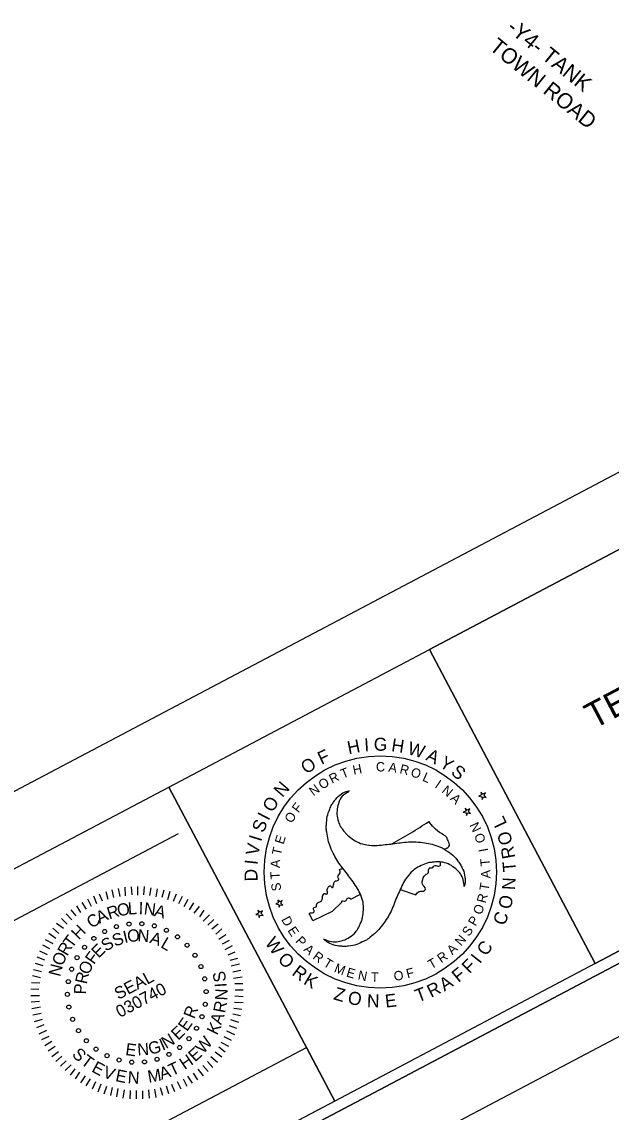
# Model space of a CAD drawing. Extents: x 1487052 to 1489663, y 496209 to 500965.
# Drawn here: x 1488873.2 to 1489101.4, y 498613.3 to 499035.6 of the extents above; entities that cross this region are included whole.
import ezdxf

# ---------------------------------------------------------------- set-up
doc = ezdxf.new("R2010")
doc.units = 0
for name, color, linetype in [('DEV TYPE 3 BARRICADE SECTION CELL', 7, 'Continuous'), ('DEV TYPE 3 BARRICADE SINGLE WITH R11-2 CELL', 7, 'Continuous'), ('DEV TYPE 3 BARRICADE WITH R11-4 M4-10L CELL', 7, 'Continuous'), ('DEV TYPE 3 BARRICADE WITH R11-4 M4-10R CELL', 7, 'Continuous'), ('Scratch_Level_0', 7, 'Continuous'), ('Scratch_Level_3', 7, 'Continuous'), ('Scratch_Level_4', 7, 'Continuous'), ('Sheet Plot Border Outside CELL', 7, 'Continuous'), ('Sheet Sticker Exception Certification CELL', 7, 'Continuous'), ('WZ OSDR CELL', 7, 'Continuous')]:
    doc.layers.add(name, color=color, linetype=linetype)

msp = doc.modelspace()

# ---------------------------------------------------------------- linework, layer by layer
at = {"layer": 'DEV TYPE 3 BARRICADE SINGLE WITH R11-2 CELL'}
msp.add_lwpolyline([(1488799.26, 499640.64), (1487561.25, 498986.94), (1488004.83, 498146.86), (1488782, 498557.22), (1488726.77, 498661.8), (1489187.62, 498905.14)], close=True, dxfattribs=at)
at = {"layer": 'DEV TYPE 3 BARRICADE WITH R11-4 M4-10L CELL'}
msp.add_circle((1489011.98, 498706.33), 44.97, dxfattribs=at)
at = {"layer": 'DEV TYPE 3 BARRICADE WITH R11-4 M4-10R CELL'}
for p, q in [((1489051.12, 498736.16), (1489050.16, 498735.65)), ((1489050.16, 498735.65), (1489051.24, 498735.49)), ((1489051.72, 498736.47), (1489050.94, 498737.19)), ((1489050.94, 498737.19), (1489051.12, 498736.16)), ((1489051.24, 498735.49), (1489051.45, 498734.42)), ((1489051.45, 498734.42), (1489051.89, 498735.38)), ((1489052.68, 498736.98), (1489051.72, 498736.47)), ((1489051.89, 498735.38), (1489052.98, 498735.23)), ((1489052.2, 498736), (1489052.68, 498736.98)), ((1489052.98, 498735.23), (1489052.2, 498736)), ((1489045.04, 498729.95), (1489044.08, 498729.45)), ((1489044.08, 498729.45), (1489045.16, 498729.29)), ((1489045.64, 498730.27), (1489044.85, 498730.99)), ((1489044.85, 498730.99), (1489045.04, 498729.95)), ((1489046.6, 498730.78), (1489045.64, 498730.27)), ((1489046.12, 498729.8), (1489046.6, 498730.78)), ((1489046.89, 498729.03), (1489046.12, 498729.8)), ((1489045.16, 498729.29), (1489045.36, 498728.22)), ((1489045.36, 498728.22), (1489045.81, 498729.18)), ((1489045.81, 498729.18), (1489046.89, 498729.03)), ((1489000.52, 498695.81), (1489004.26, 498697.75)), ((1489019.72, 498699.6), (1489025.71, 498697.48)), ((1488965.37, 498690.72), (1488964.59, 498691.44)), ((1488964.59, 498691.44), (1488964.77, 498690.4)), ((1488972.45, 498694.44), (1488971.49, 498693.94)), ((1488971.49, 498693.94), (1488972.57, 498693.78)), ((1488973.05, 498694.76), (1488972.27, 498695.48)), ((1488972.27, 498695.48), (1488972.45, 498694.44)), ((1488972.57, 498693.78), (1488972.78, 498692.71)), ((1488972.78, 498692.71), (1488973.22, 498693.67)), ((1488974.01, 498695.27), (1488973.05, 498694.76)), ((1488973.22, 498693.67), (1488974.3, 498693.51)), ((1488973.53, 498694.29), (1488974.01, 498695.27)), ((1488974.3, 498693.51), (1488973.53, 498694.29)), ((1488996.98, 498694.58), (1488993.39, 498691.09)), ((1488964.77, 498690.4), (1488963.81, 498689.89)), ((1488963.81, 498689.89), (1488964.89, 498689.74)), ((1488964.89, 498689.74), (1488965.1, 498688.67)), ((1488965.1, 498688.67), (1488965.54, 498689.63)), ((1488966.33, 498691.23), (1488965.37, 498690.72)), ((1488965.54, 498689.63), (1488966.63, 498689.47)), ((1488965.54, 498689.63), (1488966.62, 498689.47)), ((1488965.85, 498690.25), (1488966.33, 498691.23)), ((1488965.85, 498690.24), (1488966.33, 498691.23)), ((1488966.63, 498689.47), (1488965.85, 498690.25)), ((1488966.62, 498689.47), (1488965.85, 498690.24)), ((1488985.83, 498687.45), (1488984.66, 498689.83)), ((1488993.39, 498691.09), (1488985.83, 498687.45))]:
    msp.add_line(p, q, dxfattribs=at)
for start, end in [(299.0386, 303.1587), (293.5136, 293.8113)]:
    msp.add_arc((1488903.21, 498921.08), 233.19, start, end, dxfattribs=at)
for points in [[(1488999.78, 498737.85), (1488999.75, 498737.74), (1488997.69, 498736.12), (1488996.19, 498733.96), (1488995.45, 498731.5), (1488995.19, 498728.72), (1488995.76, 498725.81), (1488996.63, 498723.87), (1488997.27, 498723.05), (1488998.32, 498721.6), (1488999.32, 498720.55), (1489001.66, 498718.84), (1489004.37, 498717.42), (1489007.57, 498716.77), (1489007.84, 498716.73), (1489010.8, 498716.63), (1489013.9, 498716.92), (1489016.82, 498717.25), (1489019.85, 498717.67), (1489022.89, 498718), (1489025.82, 498717.97), (1489029.17, 498717.67), (1489032, 498717.07), (1489034.92, 498716.04), (1489036.31, 498715.46), (1489037.41, 498714.71), (1489040.01, 498712.89), (1489042.05, 498710.51), (1489043.14, 498708.96), (1489043.85, 498707.51), (1489043.97, 498707.28), (1489044.75, 498704.38), (1489044.74, 498701.58), (1489044.48, 498700.68)], [(1488989.98, 498680.47), (1488992.46, 498679.5), (1488995.04, 498679.28), (1488997.55, 498679.88), (1489000.11, 498681.05), (1489002.34, 498682.99), (1489003.58, 498684.73), (1489003.99, 498685.67), (1489004.71, 498687.3), (1489005.08, 498688.71), (1489005.45, 498691.58), (1489005.29, 498694.65), (1489004.27, 498697.73), (1489004.17, 498697.98), (1489002.74, 498700.62), (1489000.97, 498703.12), (1488999.22, 498705.5), (1488997.33, 498707.93), (1488995.5, 498710.37), (1488994.09, 498712.93), (1488992.69, 498715.99), (1488991.77, 498718.75), (1488991.23, 498721.8), (1488991.02, 498723.27), (1488991.11, 498724.6), (1488991.42, 498727.76), (1488992.43, 498730.72), (1488993.23, 498732.43), (1488994.14, 498733.75), (1488994.29, 498733.98), (1488996.38, 498736.12), (1488998.8, 498737.52), (1488999.75, 498737.74)], [(1489036.74, 498715.2), (1489038.78, 498716.62), (1489038.19, 498718.51), (1489037.45, 498719.98), (1489035.66, 498721.18), (1489032.69, 498723.54), (1489030.76, 498725.87)], [(1489044.48, 498700.68), (1489044.09, 498703.27), (1489042.99, 498705.63), (1489041.21, 498707.52), (1489038.93, 498709.13), (1489036.14, 498710.09), (1489034.03, 498710.31), (1489032.98, 498710.16), (1489031.23, 498710.02), (1489029.78, 498709.61), (1489027.15, 498708.5), (1489024.54, 498706.82), (1489022.4, 498704.38), (1489022.24, 498704.18), (1489020.67, 498701.62), (1489019.38, 498698.84), (1489018.16, 498696.14), (1489017.03, 498693.29), (1489015.81, 498690.46), (1489014.31, 498687.97), (1489012.37, 498685.21), (1489010.43, 498683.07), (1489008.09, 498681.07), (1489006.88, 498680.13), (1489005.69, 498679.57), (1489002.84, 498678.24), (1488999.73, 498677.63), (1488997.88, 498677.47), (1488996.25, 498677.62), (1488995.98, 498677.62), (1488993.09, 498678.37), (1488990.68, 498679.77), (1488989.98, 498680.47)], [(1489025.71, 498697.48), (1489026.97, 498698.72), (1489028.47, 498698.91), (1489029.13, 498699.13), (1489029.43, 498699.76), (1489028.29, 498701.56), (1489028.25, 498702.66), (1489029.48, 498705.23), (1489030.59, 498706.16), (1489030.91, 498707.8), (1489031.29, 498707.97), (1489032.04, 498707.95), (1489033.18, 498708.87), (1489034.64, 498708.59), (1489035.22, 498708.95), (1489035.2, 498710.15)], [(1488984.66, 498689.83), (1488984.47, 498690.02), (1488984.74, 498690.48), (1488986.07, 498690.61), (1488986.37, 498691.38), (1488986.1, 498691.84), (1488986.3, 498692.55), (1488987.13, 498692.8), (1488987.35, 498694), (1488987.88, 498694.51), (1488989.21, 498695.21), (1488989.95, 498697.61), (1488990.55, 498698.05), (1488990.95, 498697.72), (1488991.38, 498697.86), (1488991.4, 498699.53), (1488991.48, 498699.79), (1488992.42, 498700.93), (1488992.87, 498700.85), (1488993.28, 498700.33), (1488993.5, 498700.32), (1488993.76, 498700.81), (1488993.94, 498701.8), (1488994.66, 498702.85), (1488995.89, 498703.3), (1488995.59, 498704.36), (1488996.46, 498705.97), (1488996.45, 498706.67), (1488996.23, 498707.26)], [(1489000.52, 498695.81), (1488999.92, 498696.23), (1488999.22, 498696.09), (1488998.62, 498695.23), (1488998.01, 498694.93), (1488997.07, 498695.08), (1488996.98, 498694.58)]]:
    msp.add_spline(points, degree=3, dxfattribs=at)
at = {"layer": 'Scratch_Level_0'}
for p, q in [((1488804.45, 498652.85), (1488933.86, 498721.18)), ((1488941.13, 498718.44), (1488994.36, 498617.64))]:
    msp.add_line(p, q, dxfattribs=at)
for points in [[(1488820.13, 499708.2), (1487493.69, 499007.81), (1487983.96, 498079.29), (1489310.41, 498779.69)], [(1489239.66, 498902.65), (1489030.97, 498792.46), (1489095.17, 498670.86), (1489303.86, 498781.06)], [(1488930.15, 498739.23), (1489030.97, 498792.46), (1489095.17, 498670.86), (1488994.36, 498617.63)], [(1488753.26, 498645.82), (1488930.15, 498739.23), (1488994.36, 498617.63), (1488817.47, 498524.23)]]:
    msp.add_lwpolyline(points, close=True, dxfattribs=at)
at = {"layer": 'Scratch_Level_3'}
msp.add_lwpolyline([(1487493.69, 499007.81), (1488662.1, 499625.77), (1488820.13, 499708.2), (1489310.41, 498779.69), (1487983.96, 498079.29)], close=True, dxfattribs=at)
msp.add_lwpolyline([(1487493.69, 499007.81), (1488662.1, 499625.77), (1488820.13, 499708.2), (1489310.41, 498779.69), (1487983.96, 498079.29)], close=True, dxfattribs=at)
at = {"layer": 'Scratch_Level_4'}
for p, q in [((1488910.48, 498699.92), (1488911.11, 498696.86)), ((1488913.15, 498700.48), (1488913.23, 498697.13)), ((1488915.5, 498700.59), (1488915.85, 498697.52)), ((1488917.96, 498700.76), (1488918.03, 498697.4)), ((1488920.64, 498700.76), (1488920.27, 498697.45)), ((1488923.17, 498700.26), (1488922.68, 498697.17)), ((1488925.64, 498699.86), (1488925.04, 498696.72)), ((1488898.61, 498695.91), (1488900.12, 498693.04)), ((1488900.93, 498697.14), (1488902.11, 498694.09)), ((1488903.2, 498697.91), (1488904.38, 498695.14)), ((1488905.7, 498698.81), (1488906.55, 498695.86)), ((1488908.03, 498699.47), (1488908.66, 498696.41)), ((1488928.16, 498699.36), (1488927.45, 498696.44)), ((1488930.47, 498698.74), (1488929.59, 498695.59)), ((1488932.95, 498697.79), (1488931.79, 498694.91)), ((1488935.32, 498696.78), (1488933.82, 498694.01)), ((1488937.47, 498695.65), (1488935.97, 498692.88)), ((1488892.21, 498691.69), (1488894.17, 498689.33)), ((1488894.36, 498693.24), (1488895.98, 498690.71)), ((1488896.4, 498694.46), (1488898.13, 498691.99)), ((1488939.68, 498694.42), (1488938.01, 498691.7)), ((1488941.84, 498693.01), (1488939.83, 498690.39)), ((1488943.71, 498691.6), (1488941.98, 498688.99)), ((1488888.6, 498688.36), (1488890.77, 498686.12)), ((1488890.35, 498690.14), (1488892.58, 498687.78)), ((1488945.82, 498689.74), (1488943.42, 498687.34)), ((1488947.6, 498687.99), (1488945.24, 498685.76)), ((1488885.21, 498684.6), (1488887.55, 498682.58)), ((1488886.63, 498686.47), (1488889.35, 498684.52)), ((1488949.26, 498686.19), (1488946.79, 498684.17)), ((1488950.7, 498684.26), (1488948.34, 498682.31)), ((1488882.29, 498680.23), (1488885.23, 498678.67)), ((1488883.69, 498682.66), (1488886.42, 498680.71)), ((1488952.14, 498682.06), (1488949.45, 498680.21)), ((1488953.48, 498679.79), (1488950.72, 498678.33)), ((1488880.1, 498675.82), (1488883.09, 498674.43)), ((1488881.16, 498678.08), (1488883.99, 498676.74)), ((1488954.59, 498677.69), (1488951.83, 498676.23)), ((1488955.7, 498675.31), (1488952.93, 498674.13)), ((1488878.41, 498670.97), (1488881.4, 498670.14)), ((1488879.09, 498673.45), (1488881.96, 498672.28)), ((1488956.71, 498672.87), (1488953.76, 498672.03)), ((1488957.49, 498670.6), (1488954.31, 498669.91)), ((1488877.4, 498666.2), (1488880.44, 498665.54)), ((1488877.68, 498668.61), (1488880.78, 498667.84)), ((1488958.04, 498668.21), (1488954.87, 498667.52)), ((1488876.96, 498663.56), (1488880.15, 498663.41)), ((1488958.55, 498665.65), (1488955.15, 498665.12)), ((1488958.83, 498662.97), (1488955.7, 498663.01)), ((1488876.67, 498661.15), (1488879.86, 498660.99)), ((1488876.68, 498658.46), (1488880.03, 498658.54)), ((1488958.94, 498657.94), (1488955.69, 498658.2)), ((1488958.94, 498660.62), (1488955.86, 498660.55)), ((1488876.84, 498656.01), (1488880.08, 498656.3)), ((1488877.07, 498653.44), (1488880.41, 498654.07)), ((1488958.38, 498653.12), (1488955.24, 498653.44)), ((1488958.88, 498655.65), (1488955.52, 498655.85)), ((1488877.51, 498650.99), (1488880.69, 498651.68)), ((1488878.19, 498648.38), (1488881.24, 498649.28)), ((1488957.87, 498650.59), (1488954.84, 498651.25)), ((1488878.97, 498646.1), (1488881.9, 498647.23)), ((1488879.97, 498643.66), (1488882.9, 498645.07)), ((1488956.47, 498645.75), (1488953.65, 498646.81)), ((1488957.26, 498648), (1488954.16, 498649.05)), ((1488880.97, 498641.5), (1488883.85, 498642.74)), ((1488882.19, 498639.18), (1488884.84, 498640.86)), ((1488954.39, 498641.12), (1488951.57, 498642.45)), ((1488955.63, 498643.33), (1488952.53, 498644.66)), ((1488883.47, 498637.03), (1488886.17, 498638.88)), ((1488884.86, 498634.94), (1488887.39, 498636.84)), ((1488950.62, 498634.61), (1488948.01, 498636.62)), ((1488951.98, 498636.59), (1488949.42, 498638.49)), ((1488953.38, 498638.75), (1488950.44, 498640.31)), ((1488886.36, 498632.9), (1488888.77, 498635.02)), ((1488888.13, 498631.15), (1488890.43, 498633.22)), ((1488947.19, 498630.67), (1488945.12, 498632.97)), ((1488948.99, 498632.61), (1488946.43, 498634.79)), ((1488890.01, 498629.46), (1488892.26, 498631.63)), ((1488892.07, 498627.72), (1488893.91, 498630.11)), ((1488893.94, 498626.3), (1488895.73, 498628.8)), ((1488941.37, 498625.9), (1488939.63, 498628.38)), ((1488943.51, 498627.46), (1488941.5, 498629.93)), ((1488945.32, 498629.12), (1488943.26, 498631.42)), ((1488896.05, 498624.73), (1488897.89, 498627.4)), ((1488898.08, 498623.54), (1488899.76, 498626.26)), ((1488900.57, 498622.31), (1488901.85, 498625.25)), ((1488902.83, 498621.24), (1488903.88, 498624.34)), ((1488932.41, 498621.17), (1488931.34, 498624)), ((1488934.85, 498622.18), (1488933.44, 498625.11)), ((1488937.23, 498623.29), (1488935.77, 498626.06)), ((1488939.27, 498624.51), (1488937.53, 498627.27)), ((1488905.09, 498620.46), (1488906.19, 498623.44)), ((1488907.67, 498619.84), (1488908.33, 498622.88)), ((1488909.98, 498619.22), (1488910.52, 498622.48)), ((1488912.51, 498618.72), (1488912.94, 498621.92)), ((1488915.14, 498618.55), (1488915.29, 498621.74)), ((1488917.6, 498618.44), (1488917.58, 498621.68)), ((1488920.12, 498618.5), (1488920.05, 498621.57)), ((1488922.68, 498618.72), (1488922.39, 498621.96)), ((1488925.19, 498619.06), (1488924.68, 498622.18)), ((1488927.75, 498619.84), (1488926.9, 498622.78)), ((1488930.14, 498620.4), (1488929.23, 498623.45))]:
    msp.add_line(p, q, dxfattribs=at)
for centre in [(1488905.26, 498683.29), (1488909.85, 498685.18), (1488914.7, 498686.18), (1488919.66, 498686.28), (1488924.55, 498685.47), (1488929.2, 498683.77), (1488901.1, 498680.6), (1488933.47, 498681.24), (1488937.2, 498677.98), (1488897.5, 498677.19), (1488940.26, 498674.08), (1488894.6, 498673.17), (1488942.56, 498669.69), (1488892.48, 498668.69), (1488891.21, 498663.9), (1488944.01, 498664.95), (1488890.86, 498658.96), (1488944.57, 498660.03), (1488891.41, 498654.03), (1488944.21, 498655.08), (1488892.86, 498649.29), (1488942.95, 498650.29), (1488895.16, 498644.9), (1488940.83, 498645.81), (1488898.23, 498641), (1488937.92, 498641.79), (1488901.95, 498637.74), (1488930.16, 498635.69), (1488934.32, 498638.38), (1488906.22, 498635.21), (1488910.88, 498633.52), (1488915.77, 498632.7), (1488920.72, 498632.8), (1488925.57, 498633.81)]:
    msp.add_circle(centre, 0.788, dxfattribs=at)
at = {"layer": 'Sheet Plot Border Outside CELL'}
msp.add_lwpolyline([(1487851.5, 497981.08), (1489344.19, 498769.26), (1488830.57, 499741.98), (1487337.88, 498953.8)], close=True, dxfattribs=at)
at = {"layer": 'Sheet Sticker Exception Certification CELL'}
for p, q in [((1488806.49, 498545.01), (1488983.38, 498638.41)), ((1488983.39, 498638.4), (1488994.36, 498617.62)), ((1488994.36, 498617.63), (1488817.47, 498524.23))]:
    msp.add_line(p, q, dxfattribs=at)
at = {"layer": 'WZ OSDR CELL'}
msp.add_lwpolyline([(1489030.97, 498792.46), (1489239.66, 498902.65), (1489303.86, 498781.06), (1489095.17, 498670.86)], close=True, dxfattribs=at)

# ---------------------------------------------------------------- texts
at = {"layer": 'DEV TYPE 3 BARRICADE SECTION CELL'}
for s, p in [('-Y4- TANK', (1489060.55, 499032.49)), ('TOWN ROAD', (1489053.81, 499025.08))]:
    msp.add_text(s, height=6, rotation=320.9669, dxfattribs=at).set_placement(p)
at = {"layer": 'DEV TYPE 3 BARRICADE WITH R11-4 M4-10L CELL'}
for s, height, rotation, p in [('T', 3.63, 21.6235, (1488997.47, 498742.44)), ('L', 5.04, 115.2641, (1489061.15, 498725)), ('O', 5.04, 106.8247, (1489063.36, 498717.58)), ('R', 5.04, 100.587, (1489064.28, 498711.93)), ('T', 5.04, 94.7161, (1489064.58, 498706.55)), ('N', 5.04, 86.7271, (1489064.1, 498699.24)), ('O', 5.04, 78.2877, (1489062.49, 498691.67)), ('C', 5.04, 70.9158, (1489060.19, 498685.31)), ('W', 5.04, 305.9851, (1488967.14, 498678.84)), ('C', 5.04, 55.8384, (1489053.07, 498673.49)), ('O', 5.04, 314.9498, (1488971.98, 498672.19)), ('I', 5.04, 51.5854, (1489050.52, 498670.54)), ('R', 5.04, 323.3892, (1488977.42, 498666.69)), ('F', 5.04, 45.5978, (1489046.57, 498666.71)), ('K', 5.04, 329.6269, (1488981.93, 498663.17)), ('F', 5.04, 39.6102, (1489042.25, 498663.32)), ('T', 5.04, 20.5299, (1489026.53, 498655.79)), ('R', 5.04, 26.4007, (1489031.62, 498657.54)), ('A', 5.04, 32.6385, (1489036.81, 498659.96)), ('Z', 5.04, 344.0038, (1488993.59, 498657.06)), ('O', 5.04, 350.3584, (1488999.16, 498655.32)), ('N', 5.04, 358.7977, (1489006.78, 498653.99)), ('E', 5.04, 6.7868, (1489014.11, 498653.78))]:
    msp.add_text(s, height=height, rotation=rotation, dxfattribs=at).set_placement(p)
at = {"layer": 'DEV TYPE 3 BARRICADE WITH R11-4 M4-10R CELL'}
for s, height, rotation, p in [('H', 5.04, 11.2891, (1488999.74, 498751.88)), ('I', 5.04, 3.6391, (1489005.91, 498753.03)), ('G', 5.04, 359.3518, (1489009.42, 498753.31)), ('H', 5.04, 351.2983, (1489016.03, 498753.12)), ('W', 5.04, 343.6484, (1489022.22, 498752.09)), ('F', 5.04, 25.0926, (1488989.21, 498747.78)), ('A', 5.04, 334.6113, (1489029.28, 498749.82)), ('Y', 5.04, 327.5835, (1489034.47, 498747.31)), ('O', 5.04, 33.6, (1488983.31, 498744.04)), ('H', 3.63, 11.4673, (1489001.7, 498743.96)), ('C', 3.63, 1.3112, (1489010.34, 498745.22)), ('A', 3.63, 351.155, (1489014.96, 498745.25)), ('R', 3.63, 346.0769, (1489019.24, 498744.63)), ('O', 3.63, 340.9988, (1489023.44, 498743.55)), ('S', 5.04, 321.06, (1489038.98, 498744.42)), ('O', 3.63, 31.7797, (1488989.44, 498738.15)), ('R', 3.63, 26.7016, (1488993.27, 498740.48)), ('L', 3.63, 335.9207, (1489028, 498741.8)), ('N', 5.04, 49.4212, (1488974.09, 498734.95)), ('N', 3.63, 36.8577, (1488986.11, 498735.58)), ('I', 3.63, 325.7646, (1489032.8, 498739.24)), ('N', 3.63, 320.6865, (1489035.49, 498737.38)), ('O', 5.04, 57.9286, (1488970.26, 498729.11)), ('A', 3.63, 315.6084, (1489038.8, 498734.54)), ('I', 5.04, 62.2159, (1488968.67, 498725.97)), ('F', 3.63, 52.092, (1488980.29, 498728.98)), ('S', 5.04, 68.4199, (1488966.8, 498721.24)), ('O', 3.63, 57.1701, (1488977.67, 498724.94)), ('N', 3.63, 115.5681, (1489051.22, 498722.91)), ('O', 3.63, 110.762, (1489052.94, 498718.31)), ('V', 5.04, 79.4157, (1488964.77, 498712.46)), ('I', 5.04, 72.7073, (1488965.81, 498717.86)), ('E', 3.63, 72.4043, (1488974.48, 498716.82)), ('T', 3.63, 77.4824, (1488973.5, 498712.56)), ('I', 3.63, 100.6058, (1489053.74, 498714.49)), ('I', 5.04, 83.703, (1488964.44, 498708.95)), ('A', 3.63, 87.6386, (1488973.09, 498707.84)), ('T', 3.63, 95.5277, (1489054.49, 498708.78)), ('D', 5.04, 91.2941, (1488964.5, 498702.72)), ('T', 3.63, 92.7167, (1488973.15, 498703.59)), ('A', 3.63, 90.4496, (1489054.55, 498703.91)), ('S', 3.63, 97.7948, (1488973.68, 498699.18)), ('T', 3.63, 80.2935, (1489053.87, 498698.87)), ('R', 3.63, 75.2154, (1489052.74, 498694.04)), ('O', 3.63, 70.1373, (1489051.14, 498689.51)), ('D', 3.63, 298.1071, (1488973.56, 498687.97)), ('P', 3.63, 59.9811, (1489048.86, 498685.11)), ('E', 3.63, 303.1852, (1488975.93, 498683.72)), ('S', 3.63, 54.903, (1489046.28, 498681.14)), ('P', 3.63, 313.3414, (1488978.9, 498679.4)), ('N', 3.63, 49.825, (1489043.26, 498677.42)), ('A', 3.63, 318.4194, (1488982.04, 498676.02)), ('R', 3.63, 323.4975, (1488985.54, 498672.97)), ('R', 3.63, 34.5907, (1489035.57, 498670.92)), ('A', 3.63, 44.7469, (1489039.86, 498674.06)), ('T', 3.63, 328.5756, (1488989.62, 498670.14)), ('M', 3.63, 338.7318, (1488993.84, 498667.74)), ('T', 3.63, 29.5126, (1489031.71, 498668.61)), ('E', 3.63, 343.8099, (1488998.58, 498665.92)), ('N', 3.63, 348.8879, (1489003.08, 498664.72)), ('T', 3.63, 359.0441, (1489008.34, 498663.84)), ('O', 3.63, 9.2003, (1489017.48, 498664.12)), ('F', 3.63, 14.2784, (1489022.52, 498665.11))]:
    msp.add_text(s, height=height, rotation=rotation, dxfattribs=at).set_placement(p)
at = {"layer": 'Scratch_Level_0'}
msp.add_text('TEMPORARY TRAFFIC', height=10, rotation=27.8351, dxfattribs=at).set_placement((1489094.6, 498761.5))
at = {"layer": 'Scratch_Level_4'}
for s, height, rotation, p in [('A', 4.72, 25.81, (1488903.29, 498686.23)), ('R', 4.72, 17.8566, (1488907.06, 498687.93)), ('O', 4.72, 10.9219, (1488910.56, 498689.07)), ('L', 4.72, 3.581, (1488914.4, 498689.83)), ('I', 4.72, 358.641, (1488918.42, 498689.97)), ('N', 4.72, 352.7389, (1488920.26, 498689.96)), ('A', 4.72, 344.8402, (1488924.14, 498689.32)), ('C', 4.72, 32.775, (1488900.2, 498684.32)), ('H', 4.72, 45.5784, (1488895.22, 498679.84)), ('I', 4.7, 13.3172, (1488913.02, 498678.78)), ('O', 4.7, 5.71, (1488914.24, 498679.15)), ('N', 4.7, 355.2281, (1488917.87, 498679.51)), ('R', 4.72, 60.0105, (1488890.77, 498673.54)), ('T', 4.72, 53.2709, (1488892.61, 498676.49)), ('E', 4.7, 44.424, (1488902.92, 498672.74)), ('S', 4.7, 32.3031, (1488905.77, 498675.38)), ('S', 4.7, 20.8765, (1488909.25, 498677.36)), ('A', 4.7, 341.7789, (1488922.41, 498678.94)), ('L', 4.7, 329.3674, (1488926.64, 498677.35)), ('O', 4.72, 67.7793, (1488889.01, 498669.64)), ('F', 4.7, 54.235, (1488901.13, 498670.24)), ('N', 4.72, 75.9017, (1488888.04, 498665.59)), ('O', 4.7, 66.0869, (1488899.15, 498666.23)), ('R', 4.7, 77.5829, (1488898.34, 498662.69)), ('SEAL', 4.699, 27.8351, (1488910.59, 498656.77)), ('S', 4.72, 100.093, (1488952.4, 498664.11)), ('P', 4.7, 87.9587, (1488898.08, 498658.88)), ('030740', 4.699, 27.8351, (1488911.17, 498649.78)), ('I', 4.72, 93.8815, (1488952.61, 498661.84)), ('N', 4.72, 87.2077, (1488952.7, 498656.51)), ('R', 4.7, 68.1844, (1488939.96, 498649.19)), ('R', 4.72, 78.9854, (1488951.87, 498651.49)), ('E', 4.7, 54.9919, (1488937.16, 498644.32)), ('A', 4.72, 71.3568, (1488950.38, 498646.93)), ('E', 4.7, 43.6408, (1488933.71, 498640.94)), ('K', 4.72, 63.9761, (1488948.8, 498642.89)), ('G', 4.7, 15.3163, (1488922.87, 498635.5)), ('I', 4.7, 23.4597, (1488927.7, 498637.06)), ('N', 4.7, 30.9629, (1488929.03, 498637.76)), ('W', 4.72, 49.8409, (1488943.51, 498635.63)), ('S', 4.72, 316.0471, (1488892.33, 498635.38)), ('E', 4.7, 352.7043, (1488913.14, 498635.45)), ('N', 4.7, 3.8935, (1488918.07, 498635.23)), ('E', 4.72, 41.9998, (1488940.25, 498632.55)), ('T', 4.72, 323.4595, (1488895.7, 498632.18)), ('E', 4.72, 331.6576, (1488899.92, 498629.2)), ('T', 4.72, 25.2217, (1488931.36, 498627.19)), ('H', 4.72, 33.8463, (1488936.23, 498629.61)), ('V', 4.72, 339.7649, (1488904.27, 498627.01)), ('E', 4.72, 348.0663, (1488909.2, 498625.41)), ('N', 4.72, 356.1641, (1488914.08, 498624.55)), ('M', 4.72, 10.1721, (1488922.36, 498624.69)), ('A', 4.72, 18.0173, (1488927.26, 498625.82))]:
    msp.add_text(s, height=height, rotation=rotation, dxfattribs=at).set_placement(p)

doc.saveas('drawing.dxf')
